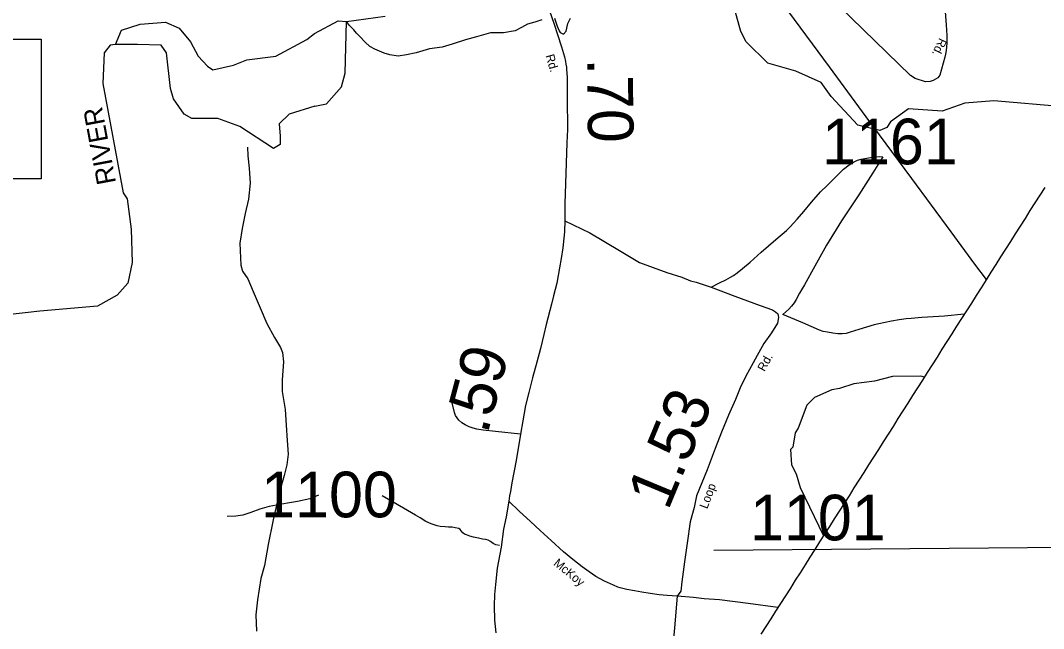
# Model space of a CAD drawing. Extents: x 2093524 to 2270757, y 289120 to 570408.
# Drawn here: x 2222555 to 2233771, y 303117 to 309784 of the extents above; entities that cross this region are included whole.
import ezdxf

# ---------------------------------------------------------------- set-up
doc = ezdxf.new("R2010")
doc.units = 0
for name, color, linetype in [('Exist Boundary Political CountyLine', 7, 'Continuous'), ('Exist Hydrographic Creek Single Shore', 7, 'Continuous'), ('Exist Hydrographic Lake Shore', 7, 'Continuous'), ('Exist Hydrographic Misc Water Feature', 7, 'Continuous'), ('Exist Hydrographic River Shore', 7, 'Continuous'), ('Exist Hydrographic River Shore Label', 7, 'Continuous'), ('Exist Road Non-System Type 51', 7, 'Continuous'), ('Exist Road Secondary Mileage Hundredths English Label', 7, 'Continuous'), ('Exist Road Secondary Structure Standard Bridge Number Label', 7, 'Continuous'), ('Exist Road Secondary Type 51 Attributed', 7, 'Continuous'), ('Exist Road Secondary Type 51 Label', 7, 'Continuous'), ('Exist Road Secondary Type 51 Number Label', 7, 'Continuous'), ('Exist Utilities Telephone Line', 7, 'Continuous'), ('Map Preparation Longitude Latitude Lines', 7, 'Continuous')]:
    doc.layers.add(name, color=color, linetype=linetype)

msp = doc.modelspace()

# ---------------------------------------------------------------- linework, layer by layer
at = {"layer": 'Exist Boundary Political CountyLine'}
for points in [[(2233783, 307952), (2233729, 307868), (2233676, 307783), (2233622, 307699), (2233568, 307614), (2233515, 307530), (2233461, 307446), (2233408, 307361), (2233354, 307277), (2233300, 307192), (2233247, 307108), (2233193, 307023), (2233140, 306939), (2233086, 306854), (2233032, 306770), (2232979, 306686), (2232925, 306601), (2232872, 306517), (2232818, 306432), (2232764, 306348), (2232710, 306263), (2232657, 306179), (2232603, 306094), (2232550, 306010), (2232496, 305926), (2232442, 305841), (2232389, 305757), (2232335, 305672), (2232282, 305588), (2232228, 305503), (2232174, 305419), (2232121, 305334), (2232067, 305250), (2232014, 305166), (2231960, 305081), (2231906, 304997), (2231852, 304912), (2231799, 304828), (2231745, 304743), (2231692, 304659), (2231638, 304574), (2231584, 304490), (2231531, 304406), (2231477, 304321), (2231424, 304237), (2231370, 304152)], [(2231370, 304152), (2231316, 304068), (2231263, 303983), (2231209, 303899), (2231156, 303815), (2231102, 303730), (2231048, 303646), (2230995, 303561), (2230941, 303477), (2230888, 303392), (2230834, 303308), (2230780, 303223), (2230726, 303139), (2230673, 303055)]]:
    msp.add_lwpolyline(points, dxfattribs=at)
at = {"layer": 'Exist Hydrographic Creek Single Shore'}
for p, q in [((2223838, 309522), (2223596, 309520)), ((2224718, 308711), (2224435, 308710))]:
    msp.add_line(p, q, dxfattribs=at)
for points in [[(2233991, 308837), (2233224, 308904), (2232908, 308878), (2232658, 308791), (2232292, 308814), (2232093, 308671), (2232052, 308612), (2231977, 308578), (2231735, 308635), (2231441, 308949), (2231332, 309105), (2231056, 309229), (2230747, 309317), (2230512, 309548), (2230452, 309664), (2230358, 310007)], [(2225783, 308844), (2225911, 308871), (2226076, 309055), (2226116, 309205), (2226128, 309772)], [(2228269, 309790), (2228193, 309766), (2228113, 309742), (2228049, 309707), (2227977, 309671), (2227851, 309649), (2227709, 309648), (2227554, 309606), (2227433, 309573), (2227286, 309523), (2227178, 309491), (2227040, 309472), (2226892, 309430), (2226786, 309409), (2226694, 309393), (2226606, 309407), (2226544, 309424), (2226440, 309468), (2226384, 309500), (2226335, 309547), (2226275, 309609), (2226239, 309645), (2226209, 309681), (2226161, 309730), (2226128, 309772)], [(2224435, 308710), (2224351, 308758), (2224233, 308924), (2224199, 309039), (2224155, 309431), (2224096, 309514), (2223838, 309522)], [(2225783, 308844), (2225501, 308758), (2225393, 308649), (2225402, 308514), (2225403, 308425), (2225328, 308381)], [(2225328, 308381), (2224960, 308621), (2224718, 308711)]]:
    msp.add_lwpolyline(points, dxfattribs=at)
at = {"layer": 'Exist Hydrographic Lake Shore'}
msp.add_lwpolyline([(2228409, 309811), (2228423, 309767), (2228439, 309721), (2228459, 309671), (2228473, 309651), (2228509, 309635), (2228537, 309667), (2228557, 309749), (2228585, 309809)], dxfattribs=at)
at = {"layer": 'Exist Hydrographic Misc Water Feature'}
for points in [[(2232464, 305875), (2232424, 305883), (2232116, 305879), (2231916, 305830)], [(2231916, 305830), (2231691, 305802), (2231534, 305749), (2231450, 305734), (2231260, 305650), (2231177, 305566), (2231079, 305315), (2231046, 305263), (2231023, 305107), (2230998, 305081), (2231007, 304913), (2231058, 304814), (2231101, 304665), (2231359, 304135)]]:
    msp.add_lwpolyline(points, dxfattribs=at)
at = {"layer": 'Exist Hydrographic River Shore'}
for points in [[(2225778, 309641), (2226037, 309781), (2226128, 309772)], [(2226128, 309772), (2226553, 309833)], [(2223596, 309520), (2223662, 309677), (2223869, 309745), (2224144, 309765), (2224295, 309700), (2224421, 309550), (2224505, 309391), (2224606, 309284), (2224664, 309244), (2224889, 309295), (2225038, 309354), (2225355, 309391), (2225695, 309574), (2225778, 309641)], [(2223596, 309520), (2223538, 309512), (2223472, 309428), (2223458, 309093), (2223682, 307895), (2223725, 307829), (2223768, 307496), (2223779, 307129), (2223731, 306904), (2223615, 306771), (2223399, 306651), (2222767, 306598), (2221893, 306500)]]:
    msp.add_lwpolyline(points, dxfattribs=at)
at = {"layer": 'Exist Road Non-System Type 51'}
for points in [[(2225044, 308395), (2225046, 308301), (2225062, 308164), (2225073, 308000), (2225056, 307824), (2225020, 307669), (2224985, 307505), (2224960, 307344), (2224969, 307183), (2224970, 307103), (2224989, 307035), (2225046, 306952), (2225107, 306811), (2225184, 306633), (2225257, 306460), (2225341, 306308), (2225405, 306199), (2225428, 306145), (2225438, 306041), (2225423, 305843), (2225423, 305715), (2225457, 305518), (2225468, 305348), (2225479, 305179), (2225491, 305031), (2225477, 304913), (2225447, 304794), (2225400, 304628), (2225361, 304469)], [(2230127, 306860), (2230220, 306907), (2230288, 306942), (2230338, 306968), (2230371, 306989), (2230411, 307017), (2230470, 307066), (2230556, 307135), (2230676, 307244), (2230837, 307384), (2230951, 307483), (2230993, 307523), (2231028, 307560), (2231070, 307606), (2231141, 307691), (2231227, 307793), (2231326, 307905), (2231397, 307976), (2231516, 308093), (2231579, 308152), (2231639, 308202), (2231686, 308230), (2231730, 308251), (2231772, 308264), (2231810, 308272), (2231872, 308283), (2231932, 308290), (2231976, 308292), (2232010, 308288), (2231900, 308115), (2231745, 307874), (2231556, 307588), (2231391, 307322), (2231264, 307089), (2231150, 306885), (2231097, 306793), (2231060, 306725), (2231036, 306690), (2231007, 306652), (2230977, 306620), (2230912, 306559)], [(2232901, 306564), (2232685, 306543), (2232438, 306526), (2232321, 306518), (2232266, 306512), (2232188, 306501), (2232104, 306486), (2231965, 306457), (2231915, 306446), (2231831, 306423), (2231747, 306396), (2231652, 306365), (2231606, 306353), (2231564, 306348), (2231516, 306350), (2231460, 306357), (2231404, 306365), (2231354, 306374), (2231314, 306388), (2231133, 306468), (2230912, 306559)], [(2228038, 305248), (2227762, 305277), (2227626, 305291), (2227559, 305302), (2227517, 305314), (2227475, 305329), (2227429, 305352), (2227393, 305374), (2227360, 305402), (2227342, 305426), (2227326, 305454), (2227315, 305486), (2227286, 305591)], [(2225824, 304579), (2225727, 304541), (2225592, 304511), (2225484, 304491), (2225361, 304469)], [(2227808, 304028), (2227768, 304035), (2227738, 304051), (2227707, 304073), (2227681, 304086), (2227656, 304094), (2227621, 304099), (2227575, 304107), (2227521, 304120), (2227481, 304132), (2227444, 304144), (2227423, 304151), (2227405, 304167), (2227388, 304189), (2227376, 304205), (2227360, 304213), (2227322, 304223), (2227286, 304228), (2227246, 304229), (2227212, 304231), (2227157, 304236), (2227122, 304244), (2227057, 304265), (2226999, 304292), (2226937, 304330), (2226887, 304359), (2226756, 304438), (2226520, 304573)], [(2225361, 304469), (2225283, 304454), (2225181, 304426), (2225082, 304389), (2224993, 304361), (2224915, 304348), (2224821, 304346)], [(2225361, 304469), (2225327, 304309), (2225270, 304040), (2225232, 303807), (2225192, 303665), (2225154, 303432), (2225137, 303266), (2225142, 303088)], [(2229754, 303472), (2229726, 303127), (2229711, 302969), (2229706, 302913), (2229676, 302727), (2229656, 302583), (2229641, 302449), (2229629, 302321), (2229598, 302094), (2229577, 301936), (2229559, 301756), (2229536, 301528), (2229520, 301328), (2229510, 301223)], [(2230859, 303348), (2230534, 303392), (2230218, 303431), (2230052, 303445), (2229932, 303456), (2229754, 303472)]]:
    msp.add_lwpolyline(points, dxfattribs=at)
at = {"layer": 'Exist Road Secondary Structure Standard Bridge Number Label'}
msp.add_lwpolyline([(2220207, 309578), (2222784, 309578), (2222784, 308049), (2220207, 308049)], close=True, dxfattribs=at)
at = {"layer": 'Exist Road Secondary Type 51 Attributed'}
for points in [[(2228355, 309891), (2228402, 309755), (2228485, 309495), (2228518, 309385), (2228529, 309333), (2228534, 309305), (2228540, 309272), (2228542, 309247), (2228547, 309163), (2228548, 309042), (2228549, 308932), (2228553, 308590), (2228545, 308442), (2228521, 307772), (2228524, 307672), (2228521, 307588)], [(2232693, 309879), (2232704, 309738), (2232710, 309618), (2232711, 309534), (2232704, 309455), (2232697, 309416), (2232687, 309383), (2232672, 309317), (2232632, 309186), (2232612, 309154), (2232560, 309126), (2232528, 309114), (2232478, 309113), (2232365, 309147), (2232311, 309181), (2231535, 309936)], [(2228521, 307588), (2228518, 307466), (2228513, 307398), (2228502, 307292), (2228484, 307176), (2228463, 307072), (2228435, 306903), (2228398, 306764), (2228378, 306673), (2228320, 306451), (2228291, 306341), (2228256, 306188), (2228216, 306039), (2228170, 305866), (2228127, 305704), (2228090, 305564), (2228064, 305396), (2228038, 305248), (2227989, 304961), (2227942, 304715), (2227927, 304621), (2227918, 304571), (2227908, 304513)], [(2228521, 307588), (2228798, 307455), (2229121, 307262), (2229343, 307129), (2229640, 307021), (2229805, 306968), (2229901, 306931), (2229964, 306916), (2230127, 306860), (2230388, 306761), (2230663, 306660), (2230799, 306610), (2230834, 306591), (2230859, 306568), (2230861, 306548), (2230864, 306528), (2230853, 306465), (2230787, 306361), (2230704, 306243), (2230631, 306112), (2230586, 306032), (2230506, 305883), (2230446, 305756), (2230393, 305630), (2230317, 305455), (2230241, 305272), (2230172, 305090)], [(2230172, 305090), (2230084, 304857), (2229966, 304571), (2229939, 304443), (2229896, 304287), (2229865, 304054), (2229836, 303850), (2229807, 303628), (2229793, 303526), (2229754, 303472), (2229644, 303478), (2229558, 303487), (2229457, 303502), (2229367, 303515), (2229286, 303530), (2229201, 303547), (2229129, 303564), (2229103, 303572), (2229055, 303592), (2228959, 303637), (2228863, 303689), (2228789, 303739), (2228712, 303795), (2228609, 303873), (2228507, 303957), (2228373, 304084), (2228254, 304193), (2228147, 304291), (2228022, 304406), (2227908, 304513)], [(2227908, 304513), (2227880, 304342), (2227850, 304206), (2227825, 304009), (2227781, 303779), (2227764, 303600), (2227753, 303489), (2227748, 303366), (2227750, 303208), (2227766, 303070)]]:
    msp.add_lwpolyline(points, dxfattribs=at)
at = {"layer": 'Exist Utilities Telephone Line'}
msp.add_lwpolyline([(2229784, 311506), (2230157, 310998), (2230554, 310455), (2230976, 309878), (2231421, 309277), (2231823, 308728), (2232322, 308050), (2232755, 307465), (2233015, 307112), (2233142, 306943)], dxfattribs=at)
at = {"layer": 'Map Preparation Longitude Latitude Lines'}
msp.add_line((2230155, 303977), (2236474, 304028), dxfattribs=at)

# ---------------------------------------------------------------- texts
at = {"layer": 'Exist Hydrographic River Shore Label'}
msp.add_text('RIVER', height=210, rotation=100.5927, dxfattribs=at).set_placement((2223605, 308005))
at = {"layer": 'Exist Road Secondary Mileage Hundredths English Label'}
for s, rotation, p in [('.70', 270.659, (2228767, 309369)), ('.59', 75.0686, (2227674, 305238)), ('1.53', 67.469, (2229653, 304401))]:
    msp.add_text(s, height=500, rotation=rotation, dxfattribs=at).set_placement(p)
at = {"layer": 'Exist Road Secondary Type 51 Label'}
for s, rotation, p in [('Rd.', 244.9229, (2232629, 309599)), ('Rd.', 286.0177, (2228311, 309399)), ('Rd.', 61.0405, (2230711, 305928)), ('Loop', 69.6285, (2230084, 304423)), ('McKoy', 320.508, (2228392, 303820))]:
    msp.add_text(s, height=95, rotation=rotation, dxfattribs=at).set_placement(p)
at = {"layer": 'Exist Road Secondary Type 51 Number Label'}
for s, p in [('1161', (2231343, 308207)), ('1100', (2225194, 304337)), ('1101', (2230553, 304084))]:
    msp.add_text(s, height=500, dxfattribs=at).set_placement(p)

doc.saveas('drawing.dxf')
